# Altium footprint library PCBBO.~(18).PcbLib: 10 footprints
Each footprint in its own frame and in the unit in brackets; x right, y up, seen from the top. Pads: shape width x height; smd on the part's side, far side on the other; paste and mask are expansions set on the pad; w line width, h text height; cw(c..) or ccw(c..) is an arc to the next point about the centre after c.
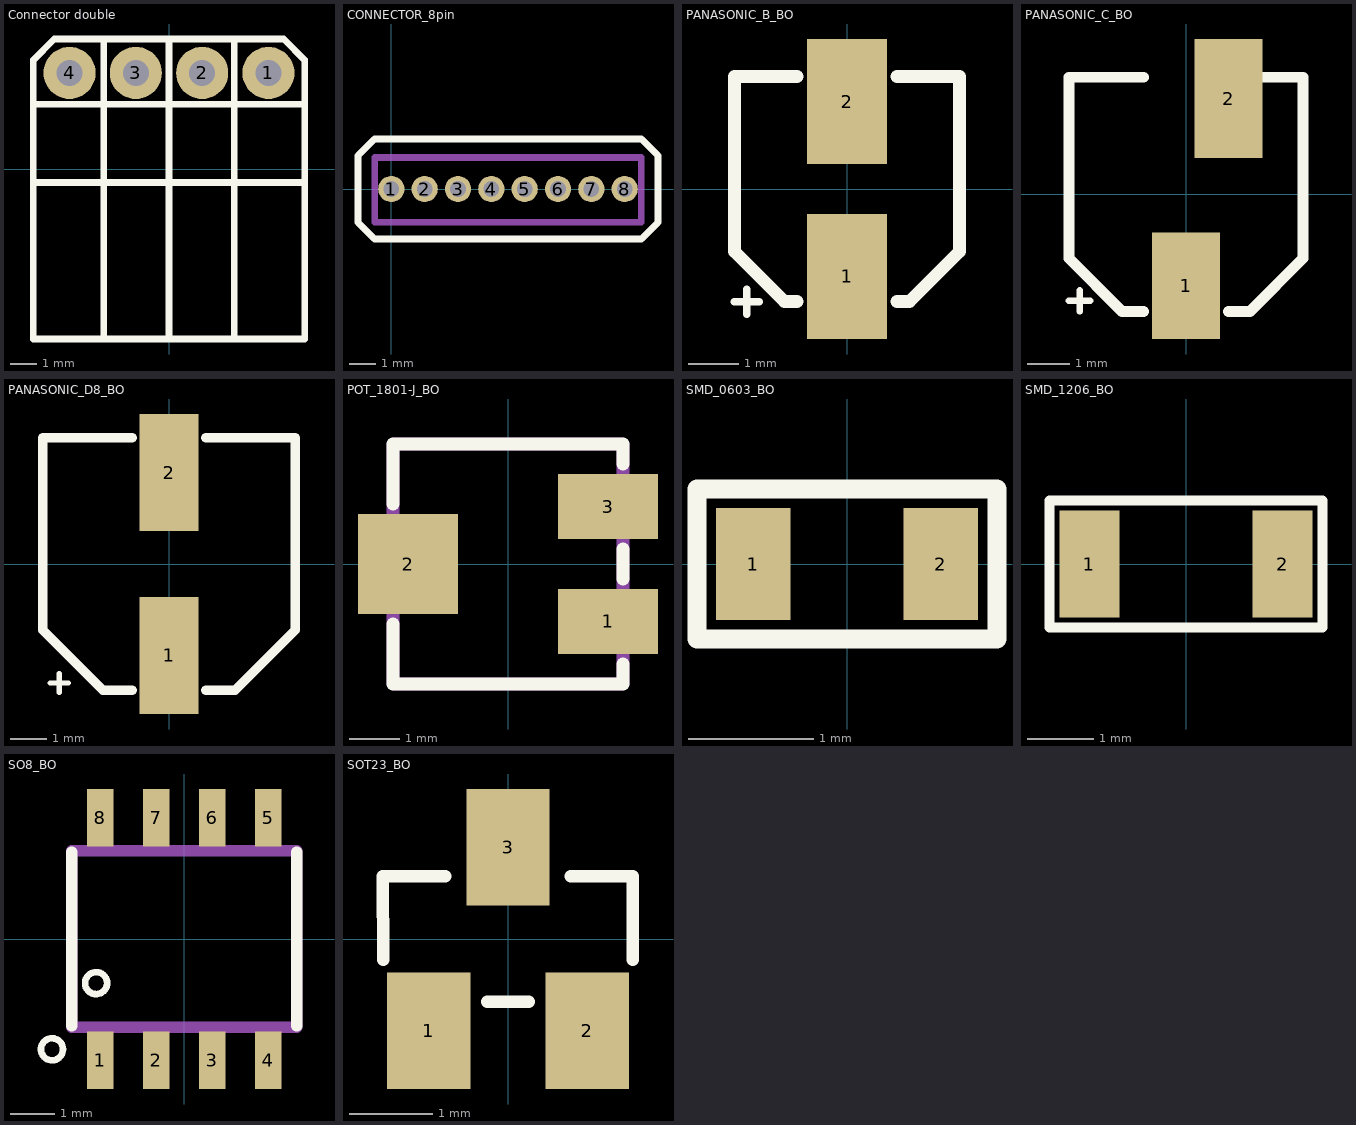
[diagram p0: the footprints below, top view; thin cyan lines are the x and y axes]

## Connector double [mm]
pads (4):
  round 2 hole 1: 1(3.81,3.7) 2(1.27,3.7) 3(-1.27,3.7) 4(-3.81,3.7)
Top Overlay:
  lines w0.254: -5.2,-0.5 5.2,-0.5 ; -5.2,2.5 5.2,2.5 ; -2.5,-6.5 -2.5,5 0,5 0,-6.5 2.5,-6.5 2.5,5 ; -5.2,-6.5 -5.2,4.2 -4.4,5 4.4,5 5.2,4.2 5.2,-6.5 -5.2,-6.5
3D body "User Library-header90-4.STEP": height 3.04, standoff -2.5, extent -5.08,-6.36 5.08,4

## CONNECTOR_8pin [mm]
pads (8):
  round 1 hole 0.6: 1(0,0) 2(1.27,0) 3(2.54,0) 4(3.81,0) 5(5.08,0) 6(6.35,0) 7(7.62,0) 8(8.89,0)
Top Overlay:
  lines w0.254: -1.27,-1.27 -0.635,-1.905 9.525,-1.905 10.16,-1.27 10.16,1.27 9.525,1.905 -0.635,1.905 -1.27,1.27 -1.27,-1.27
Mechanical 13:
  lines w0.254: -0.635,-1.27 -0.635,1.2 9.525,1.2 9.525,-1.27 -0.635,-1.27
3D body "User Library-PIN-Header-1_27_1x2.step": height 4.2, standoff -3.05, extent 6.985,-1.2 9.525,1.2
3D body "User Library-PIN-Header-1_27_1x2.step": height 4.2, standoff -3.05, extent 4.445,-1.2 6.985,1.2
3D body "User Library-PIN-Header-1_27_1x2.step": height 4.2, standoff -3.05, extent 1.905,-1.2 4.445,1.2
3D body "User Library-PIN-Header-1_27_1x2.step": height 4.2, standoff -3.05, extent -0.635,-1.2 1.905,1.2

## PANASONIC_B_BO [mm]
pads (2):
  rect 1.6x2.5 smd: 1(0,-1.75) 2(0,1.75)
Top Overlay:
  lines w0.15: -2.25,-2.25 -1.75,-2.25 ; -2,-2.5 -2,-2
  lines w0.254: -1,-2.25 -1.25,-2.25 -2.25,-1.25 -2.25,2.25 -1,2.25 ; 1,-2.25 1.25,-2.25 2.25,-1.25 2.25,2.25 1,2.25
3D body: height 0.3, standoff 0, extent -0.35,-2.5 0.35,-1
3D body: height 0.3, standoff 0, extent -0.35,1 0.35,2.5
3D body: height 1, standoff 0, extent -2.25,-2.25 2.25,2.25
3D body: height 2, standoff 1.5, extent -2.05,-2.05 2.05,2.05
3D body: height 1.5, standoff 0, extent -2.15,-2.147 2.15,2.147
3D body: height 6, standoff 2, extent -2.15,-2.147 2.15,2.147

## PANASONIC_C_BO [mm]
pads (2):
  rect 1.6x2.5 smd: 1(0,-2.147)
  rect 1.6x2.8 smd: 2(1,2.25)
Top Overlay:
  lines w0.15: -2.75,-2.5 -2.25,-2.5 ; -2.5,-2.75 -2.5,-2.25
  lines w0.254: -1,-2.75 -1.5,-2.75 -2.75,-1.5 -2.75,2.75 -1,2.75 ; 1,-2.75 1.5,-2.75 2.75,-1.5 2.75,2.75 1,2.75
3D body: height 6, standoff 2, extent -2.6,-2.6 2.6,2.6
3D body: height 1.5, standoff 0, extent -2.6,-2.6 2.6,2.6
3D body: height 2, standoff 1.5, extent -2.5,-2.497 2.5,2.497
3D body: height 0.3, standoff 0, extent -0.35,1.5 0.35,3
3D body: height 0.3, standoff 0, extent -0.35,-3 0.35,-1.5
3D body: height 1, standoff 0, extent -2.75,-2.75 2.75,2.75

## PANASONIC_D8_BO [mm]
pads (2):
  rect 1.6x3.2 smd: 1(0,-2.497) 2(0,2.497)
Top Overlay:
  lines w0.15: -3.25,-3.25 -2.75,-3.25 ; -3,-3.5 -3,-3
  lines w0.254: -1,-3.45 -1.8,-3.45 -3.45,-1.8 -3.45,3.45 -1,3.45 ; 1,-3.45 1.8,-3.45 3.45,-1.8 3.45,3.45 1,3.45
3D body: height 0.3, standoff 0, extent -0.35,-3 0.35,-1.5
3D body: height 0.3, standoff 0, extent -0.35,1.5 0.35,3
3D body: height 1, standoff 0, extent -3.45,-3.4 3.45,3.45
3D body: height 2, standoff 1.5, extent -3.1,-3.075 3.1,3.125
3D body: height 1.5, standoff 0, extent -3.2,-3.172 3.2,3.222
3D body: height 8, standoff 2, extent -3.2,-3.172 3.2,3.222

## POT_1801-J_BO [mm]
pads (3):
  rect 2x1.3 smd: 1(2,-1.15) 3(2,1.15)
  rect 2x2 smd: 2(-2,0)
Top Overlay:
  lines w0.254: -2.3,-1.2 -2.3,-2.4 2.3,-2.4 2.3,-2 ; -2.3,1.2 -2.3,2.4 2.3,2.4 2.3,2 ; 2.3,-0.3 2.3,0.3
Mechanical 13:
  lines w0.254: -2.3,-2.4 -2.3,2.4 2.3,2.4 2.3,-2.4 -2.3,-2.4
3D body: height 3.5, standoff 0.2, extent -2.3,-2.4 2.3,2.4
3D body: height 0.5, standoff 0, extent -2.5,-0.75 -1.4,0.75
3D body: height 0.5, standoff 0, extent 1.3,0.6 2.625,1.7
3D body: height 0.5, standoff 0, extent 1.3,-1.7 2.625,-0.6
3D body: height 3.24, standoff 1.75, extent -2.4,-2.2 -1.4,-0.703

## SMD_0603_BO [mm]
pads (2):
  rect 0.6x0.9 smd: 1(-0.75,0) 2(0.75,0)
Top Overlay:
  lines w0.15: -1.2,-0.6 1.2,-0.6 1.2,0.6 -1.2,0.6 -1.2,-0.6
3D body: height 0.5, standoff 0, extent -0.775,-0.425 -0.372,0.425
3D body: height 0.5, standoff 0, extent 0.341,-0.425 0.744,0.425
3D body: height 0.5, standoff 0, extent -0.372,-0.425 0.341,0.425

## SMD_1206_BO [mm]
pads (2):
  rect 0.9x1.6 smd: 1(-1.45,0) 2(1.45,0)
Top Overlay:
  lines w0.15: -2.05,-0.95 -2.05,0.95 2.05,0.95 2.05,-0.95 -2.05,-0.95
3D body: height 0.5, standoff 0, extent -1,-0.8 1,0.809
3D body: height 0.5, standoff 0, extent 1,-0.8 1.6,0.809
3D body: height 0.5, standoff 0, extent -1.6,-0.8 -1,0.825

## SO8_BO [mm]
pads (8):
  rect 0.6x1.3 smd: 1(-1.905,-2.75) 2(-0.635,-2.75) 3(0.635,-2.75) 4(1.905,-2.75) 5(1.905,2.75) 6(0.635,2.75) 7(-0.635,2.75) 8(-1.905,2.75)
Top Overlay:
  circle w0.15: c-2,-1 r0.25
  circle w0.15: c-3,-2.5 r0.25
  lines w0.254: -2.55,-1.975 -2.55,1.975 ; 2.55,-1.975 2.55,1.975
Mechanical 13:
  lines w0.254: -2.55,-2 2.55,-2 2.55,2 -2.55,2 -2.55,-2
3D body "User Library-SOIC-8-1.step": height 1.75, standoff 0, extent -2.45,-3 2.45,3

## SOT23_BO [mm]
pads (3):
  rect 1x1.4 smd: 1(-0.95,-1.1) 2(0.95,-1.1) 3(0,1.1)
Top Overlay:
  lines w0.15: -1.5,-0.25 -1.5,0.75 -1,0.75 -0.75,0.75 ; -0.25,-0.75 0.25,-0.75 ; 0.75,0.75 1.5,0.75 1.5,-0.25
3D body "CircuitWorks-SOT-23.step": height 1.05, standoff -0.05, extent -1.5,-1.25 1.5,1.25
